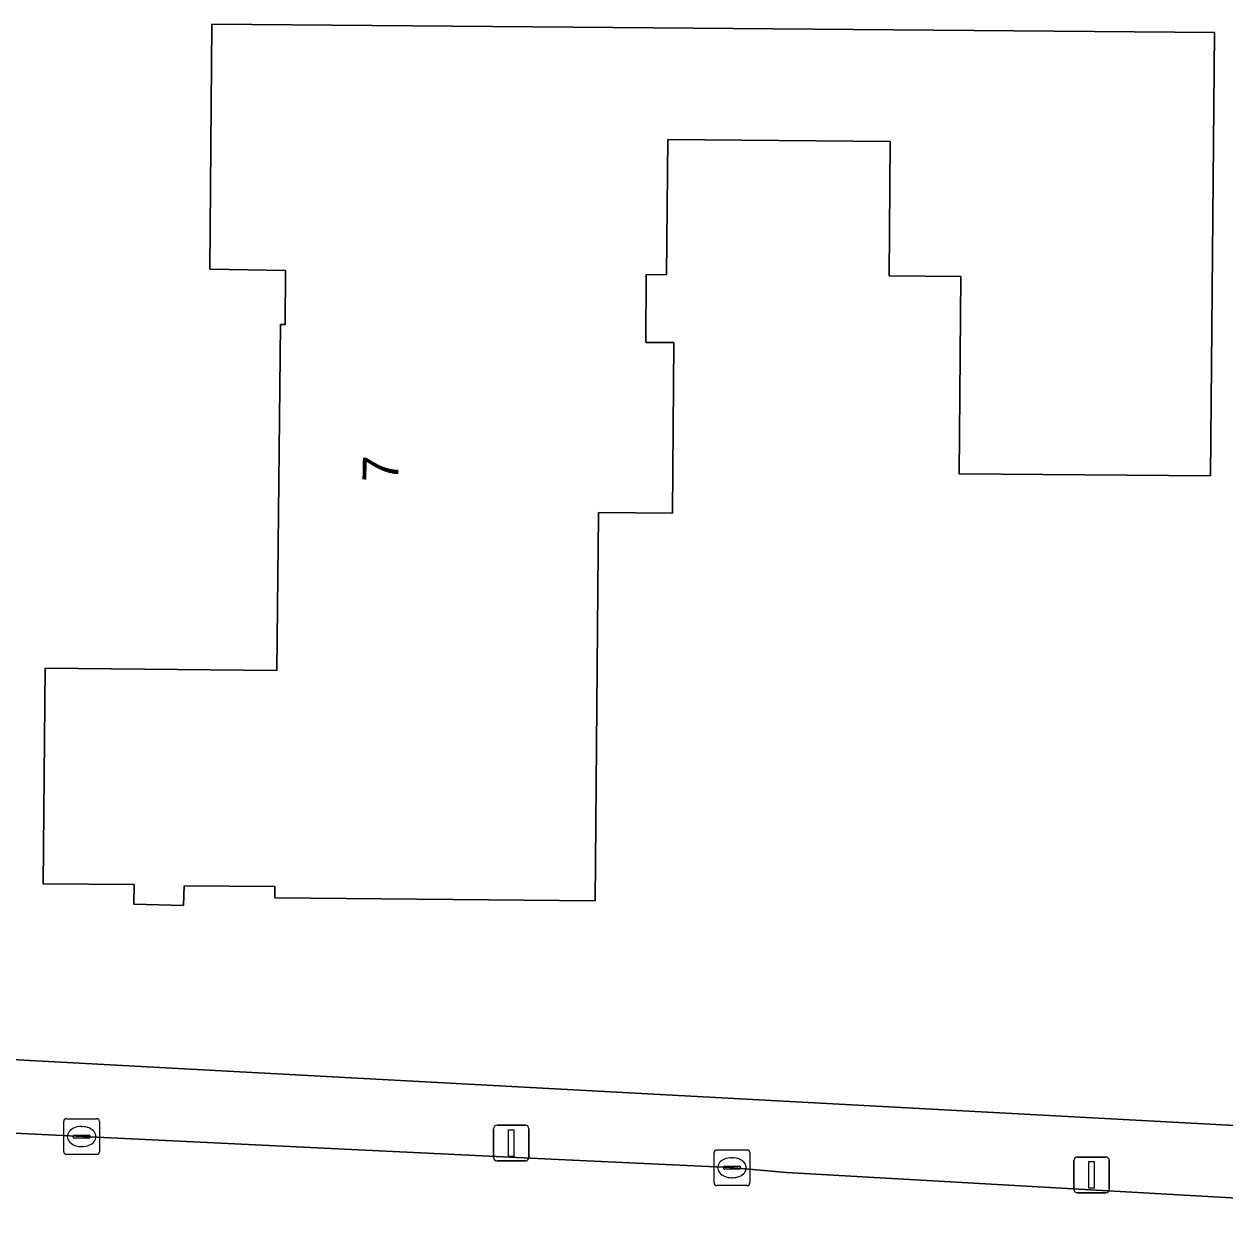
# Model space of a CAD drawing. Extents: x 161258 to 161838, y 380833 to 381727.
# Drawn here: x 161579.78 to 161613.37, y 381186.81 to 381220.32 of the extents above; entities that cross this region are included whole.
import ezdxf

# ---------------------------------------------------------------- set-up
doc = ezdxf.new("R2010")
doc.units = 0
for name, color, linetype in [('IMGEO_Erf', 7, 'Continuous'), ('IMGEO_Kolk', 7, 'Continuous'), ('IMGEO_Lichtmast', 7, 'Continuous'), ('IMGEO_Pand', 7, 'Continuous'), ('IMGEO_Pand_nummerreeks', 7, 'Continuous'), ('IMGEO_Rijbaan_lokaal_open', 7, 'Continuous'), ('IMGEO_Voetpad_open', 7, 'Continuous')]:
    doc.layers.add(name, color=color, linetype=linetype)

msp = doc.modelspace()

# ---------------------------------------------------------------- linework, layer by layer
at = {"layer": 'IMGEO_Erf'}
msp.add_lwpolyline([(161613.076, 381220.081), (161612.97, 381207.678), (161605.94, 381207.738), (161605.987, 381213.258), (161603.977, 381213.275), (161604.009, 381217.035), (161597.789, 381217.088), (161597.757, 381213.308), (161597.187, 381213.313), (161597.171, 381211.413), (161597.961, 381211.406), (161597.92, 381206.637), (161595.85, 381206.654), (161595.758, 381195.795), (161586.798, 381195.871), (161586.801, 381196.191), (161584.259, 381196.213), (161584.246, 381195.661), (161582.854, 381195.695), (161582.867, 381196.252), (161580.317, 381196.27), (161580.372, 381202.296), (161586.851, 381202.237), (161586.958, 381211.913), (161587.088, 381211.912), (161587.096, 381213.428), (161584.979, 381213.461), (161585.037, 381220.32)], close=True, dxfattribs=at)
msp.add_lwpolyline([(161578.21, 381191.415), (161643.179, 381187.909)], dxfattribs=at)
at = {"layer": 'IMGEO_Kolk'}
for p, q in [((161580.895, 381188.771), (161580.895, 381189.623)), ((161580.97, 381189.697), (161581.822, 381189.697)), ((161581.383, 381189.477), (161581.408, 381189.477)), ((161581.896, 381189.623), (161581.896, 381188.771)), ((161581.154, 381189.191), (161581.154, 381189.203)), ((161581.592, 381189.154), (161581.194, 381189.154)), ((161581.197, 381189.24), (161581.595, 381189.24)), ((161581.638, 381189.203), (161581.638, 381189.191)), ((161581.406, 381188.917), (161581.381, 381188.917)), ((161599.159, 381188.826), (161600.011, 381188.826)), ((161581.822, 381188.697), (161580.97, 381188.697)), ((161599.084, 381187.9), (161599.084, 381188.752)), ((161599.572, 381188.606), (161599.597, 381188.606)), ((161600.085, 381188.752), (161600.085, 381187.9)), ((161599.343, 381188.32), (161599.343, 381188.332)), ((161599.781, 381188.283), (161599.383, 381188.283)), ((161599.386, 381188.369), (161599.784, 381188.369)), ((161599.827, 381188.332), (161599.827, 381188.32)), ((161600.011, 381187.826), (161599.159, 381187.826)), ((161599.595, 381188.046), (161599.57, 381188.046))]:
    msp.add_line(p, q, dxfattribs=at)
for points in [[(161580.895, 381188.771), (161580.895, 381189.623)], [(161580.97, 381189.697), (161581.822, 381189.697)], [(161581.896, 381189.623), (161581.896, 381188.771)], [(161599.159, 381188.826), (161600.011, 381188.826)], [(161581.822, 381188.697), (161580.97, 381188.697)], [(161599.084, 381187.9), (161599.084, 381188.752)], [(161600.085, 381188.752), (161600.085, 381187.9)], [(161600.011, 381187.826), (161599.159, 381187.826)]]:
    msp.add_lwpolyline(points, dxfattribs=at)
for centre, radius, start, end in [((161580.972, 381189.621), 0.0765, 91.552, 178.448), ((161580.972, 381189.621), 0.0765, 91.552, 178.448), ((161581.82, 381189.621), 0.0765, 1.552, 88.448), ((161581.82, 381189.621), 0.0765, 1.552, 88.448), ((161581.194, 381189.2), 0.0403, 85.8775, 175.7526), ((161581.191, 381189.19), 0.0366, 178.938, 274.7102), ((161581.595, 381189.197), 0.043, 264.8664, 352.4533), ((161581.599, 381189.202), 0.0386, 1.7309, 96.639), ((161580.972, 381188.773), 0.0765, 181.552, 268.448), ((161580.972, 381188.773), 0.0765, 181.552, 268.448), ((161581.82, 381188.773), 0.0765, 271.552, 358.448), ((161581.82, 381188.773), 0.0765, 271.552, 358.448), ((161599.161, 381188.75), 0.0765, 91.552, 178.448), ((161599.161, 381188.75), 0.0765, 91.552, 178.448), ((161600.009, 381188.75), 0.0765, 1.552, 88.448), ((161600.009, 381188.75), 0.0765, 1.552, 88.448), ((161599.383, 381188.329), 0.0403, 85.8775, 175.7526), ((161599.38, 381188.319), 0.0366, 178.938, 274.7102), ((161599.784, 381188.326), 0.043, 264.8664, 352.4533), ((161599.788, 381188.331), 0.0386, 1.7309, 96.639), ((161599.161, 381187.902), 0.0765, 181.552, 268.448), ((161599.161, 381187.902), 0.0765, 181.552, 268.448), ((161600.009, 381187.902), 0.0765, 271.552, 358.448), ((161600.009, 381187.902), 0.0765, 271.552, 358.448)]:
    msp.add_arc(centre, radius, start, end, dxfattribs=at)
for centre, major_axis, ratio, start_param, end_param in [((161581.382, 381189.197), (-0.387, 0.002), 0.722429, 4.712389, 7.853982), ((161581.407, 381189.197), (-0.39, 0.002), 0.717154, 1.570796, 4.712389), ((161599.571, 381188.326), (-0.387, 0.002), 0.722429, 4.712389, 7.853982), ((161599.596, 381188.326), (-0.39, 0.002), 0.717154, 1.570796, 4.712389)]:
    msp.add_ellipse(centre, major_axis=major_axis, ratio=ratio, start_param=start_param, end_param=end_param, dxfattribs=at)
at = {"layer": 'IMGEO_Lichtmast'}
for p, q in [((161593.016, 381189.514), (161593.806, 381189.514)), ((161593.806, 381189.514), (161593.016, 381189.514)), ((161592.916, 381188.614), (161592.916, 381189.414)), ((161592.916, 381189.414), (161592.916, 381188.614)), ((161593.906, 381189.414), (161593.906, 381188.614)), ((161593.906, 381188.614), (161593.906, 381189.414)), ((161593.806, 381188.514), (161593.016, 381188.514)), ((161593.016, 381188.514), (161593.806, 381188.514)), ((161609.148, 381187.725), (161609.148, 381188.525)), ((161609.148, 381188.525), (161609.148, 381187.725)), ((161609.248, 381188.625), (161610.038, 381188.625)), ((161610.038, 381188.625), (161609.248, 381188.625)), ((161610.138, 381188.525), (161610.138, 381187.725)), ((161610.138, 381187.725), (161610.138, 381188.525)), ((161610.038, 381187.625), (161609.248, 381187.625)), ((161609.248, 381187.625), (161610.038, 381187.625))]:
    msp.add_line(p, q, dxfattribs=at)
for points in [[(161593.336, 381189.389), (161593.486, 381189.389), (161593.486, 381188.639), (161593.336, 381188.639), (161593.336, 381189.389)], [(161609.568, 381188.5), (161609.718, 381188.5), (161609.718, 381187.75), (161609.568, 381187.75), (161609.568, 381188.5)]]:
    msp.add_lwpolyline(points, dxfattribs=at)
for centre, start, end in [((161593.016, 381189.414), 90, 180), ((161593.016, 381189.414), 90, 180), ((161593.806, 381189.414), 0, 90), ((161593.806, 381189.414), 360, 90), ((161593.016, 381188.614), 180, 270), ((161593.016, 381188.614), 180, 270), ((161593.806, 381188.614), 270, 0), ((161593.806, 381188.614), 270, 0), ((161609.248, 381188.525), 90, 180), ((161609.248, 381188.525), 90, 180), ((161610.038, 381188.525), 0, 90), ((161610.038, 381188.525), 360, 90), ((161609.248, 381187.725), 180, 270), ((161609.248, 381187.725), 180, 270), ((161610.038, 381187.725), 270, 0), ((161610.038, 381187.725), 270, 0)]:
    msp.add_arc(centre, 0.1, start, end, dxfattribs=at)
at = {"layer": 'IMGEO_Pand'}
msp.add_lwpolyline([(161597.757, 381213.308), (161597.789, 381217.088), (161604.009, 381217.035), (161603.977, 381213.275), (161605.987, 381213.258), (161605.94, 381207.738), (161612.97, 381207.678), (161613.076, 381220.081), (161585.037, 381220.32), (161584.979, 381213.461), (161587.096, 381213.428), (161587.088, 381211.912), (161586.958, 381211.913), (161586.851, 381202.237), (161580.372, 381202.296), (161580.317, 381196.27), (161582.867, 381196.252), (161582.854, 381195.695), (161584.246, 381195.661), (161584.259, 381196.213), (161586.801, 381196.191), (161586.798, 381195.871), (161595.758, 381195.795), (161595.85, 381206.654), (161597.92, 381206.637), (161597.961, 381211.406), (161597.171, 381211.413), (161597.187, 381213.313)], close=True, dxfattribs=at)
at = {"layer": 'IMGEO_Rijbaan_lokaal_open'}
msp.add_lwpolyline([(161616.166, 381187.333), (161601.106, 381188.192), (161599.538, 381188.329), (161594.72, 381188.551), (161578.352, 381189.346), (161578.149, 381185.166), (161578.476, 381185.106), (161582.962, 381184.838), (161587.685, 381184.756), (161595.649, 381184.269), (161605.573, 381183.794), (161605.683, 381183.787), (161606.069, 381183.763), (161609.697, 381183.539), (161613.779, 381183.287)], dxfattribs=at)
at = {"layer": 'IMGEO_Voetpad_open'}
for points in [[(161578.21, 381191.415), (161578.352, 381189.346), (161594.72, 381188.551), (161599.538, 381188.329), (161601.106, 381188.192), (161616.166, 381187.333), (161627.28, 381186.753), (161639.431, 381186.067), (161646.327, 381185.682)], [(161643.179, 381187.909), (161578.21, 381191.415)]]:
    msp.add_lwpolyline(points, dxfattribs=at)

# ---------------------------------------------------------------- texts
at = {"layer": 'IMGEO_Pand_nummerreeks'}
msp.add_text('7', height=1, rotation=88.7475, dxfattribs=at).set_placement((161590.247, 381207.489))

doc.saveas('drawing.dxf')
